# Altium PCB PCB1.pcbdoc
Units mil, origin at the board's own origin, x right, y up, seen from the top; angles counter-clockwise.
Board outline 4565 x 3530 mil, 4 copper layers (Top Layer, Inner1, Inner2, Bottom Layer); 96 components, 68 nets, 367 pads, 177 vias.
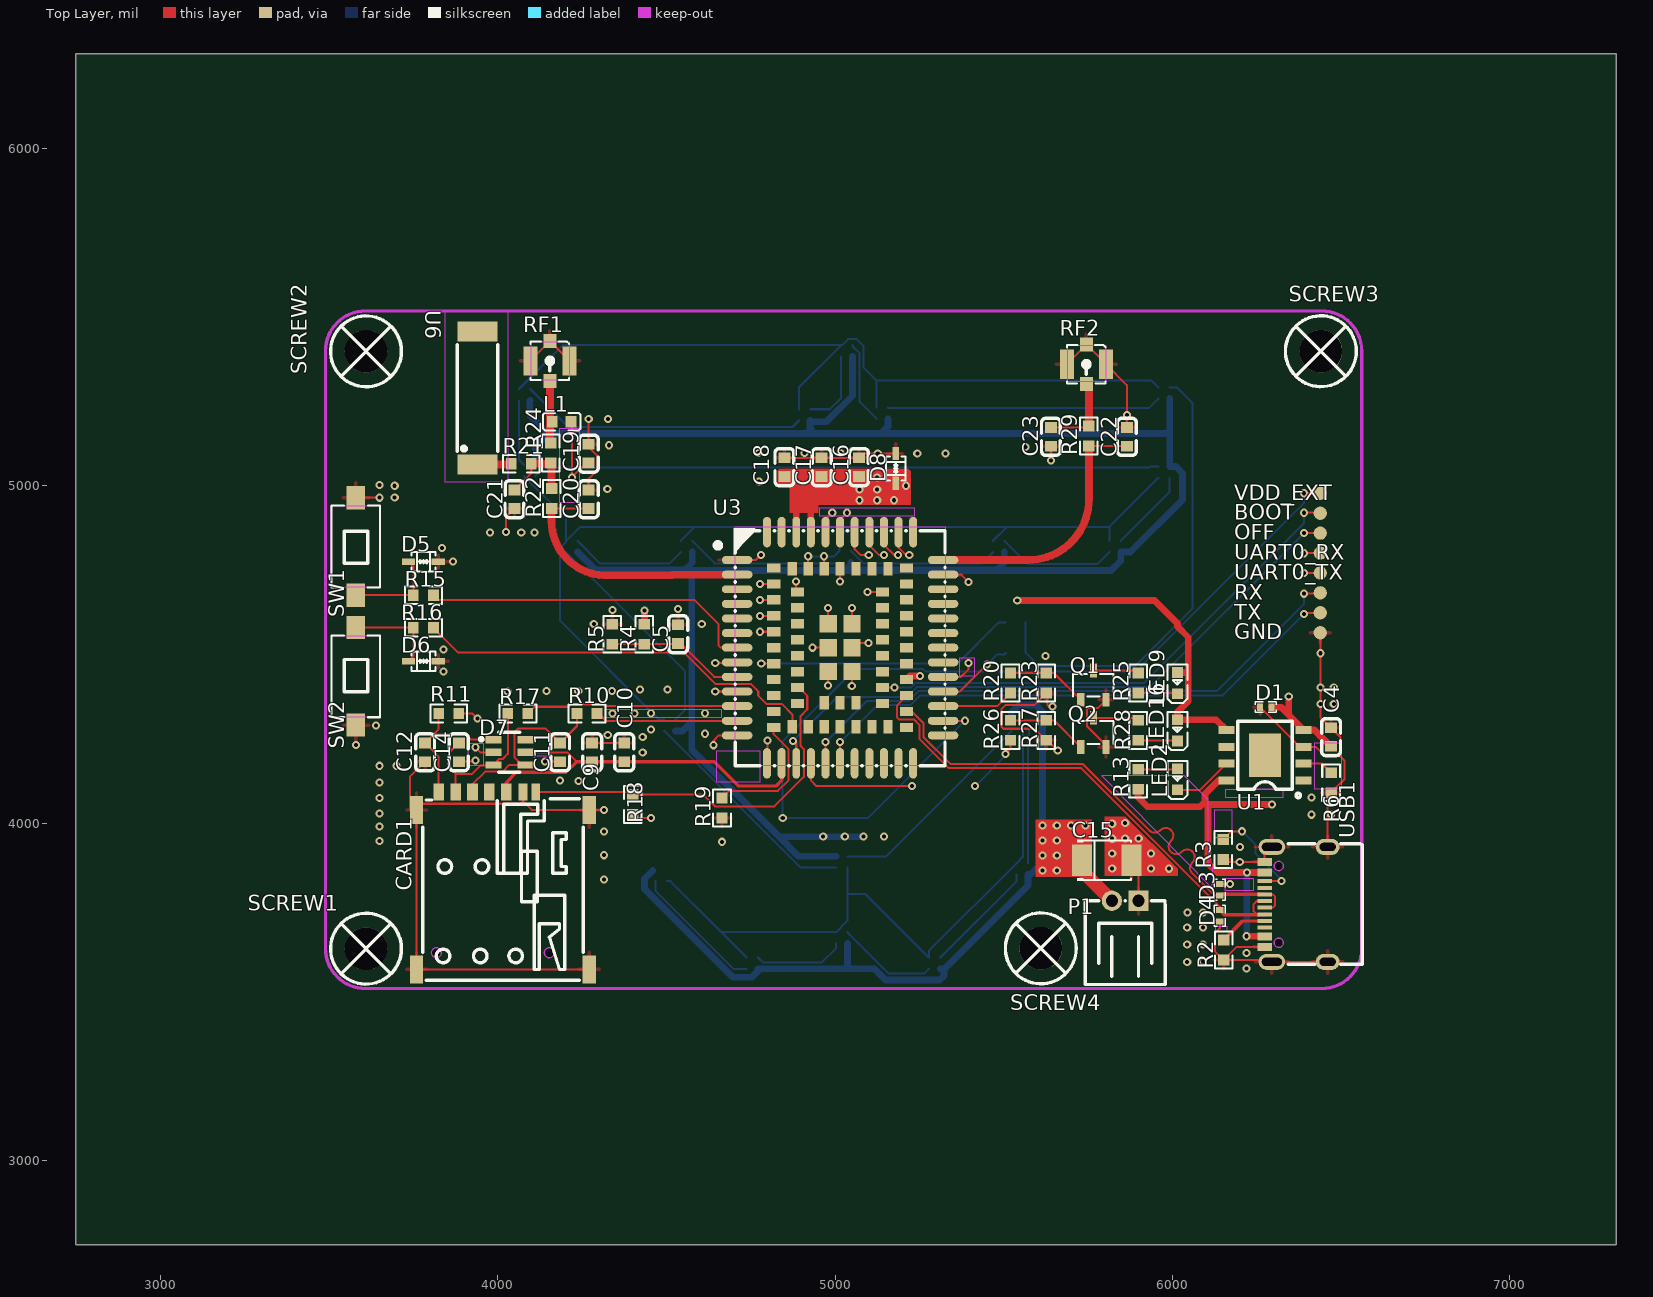
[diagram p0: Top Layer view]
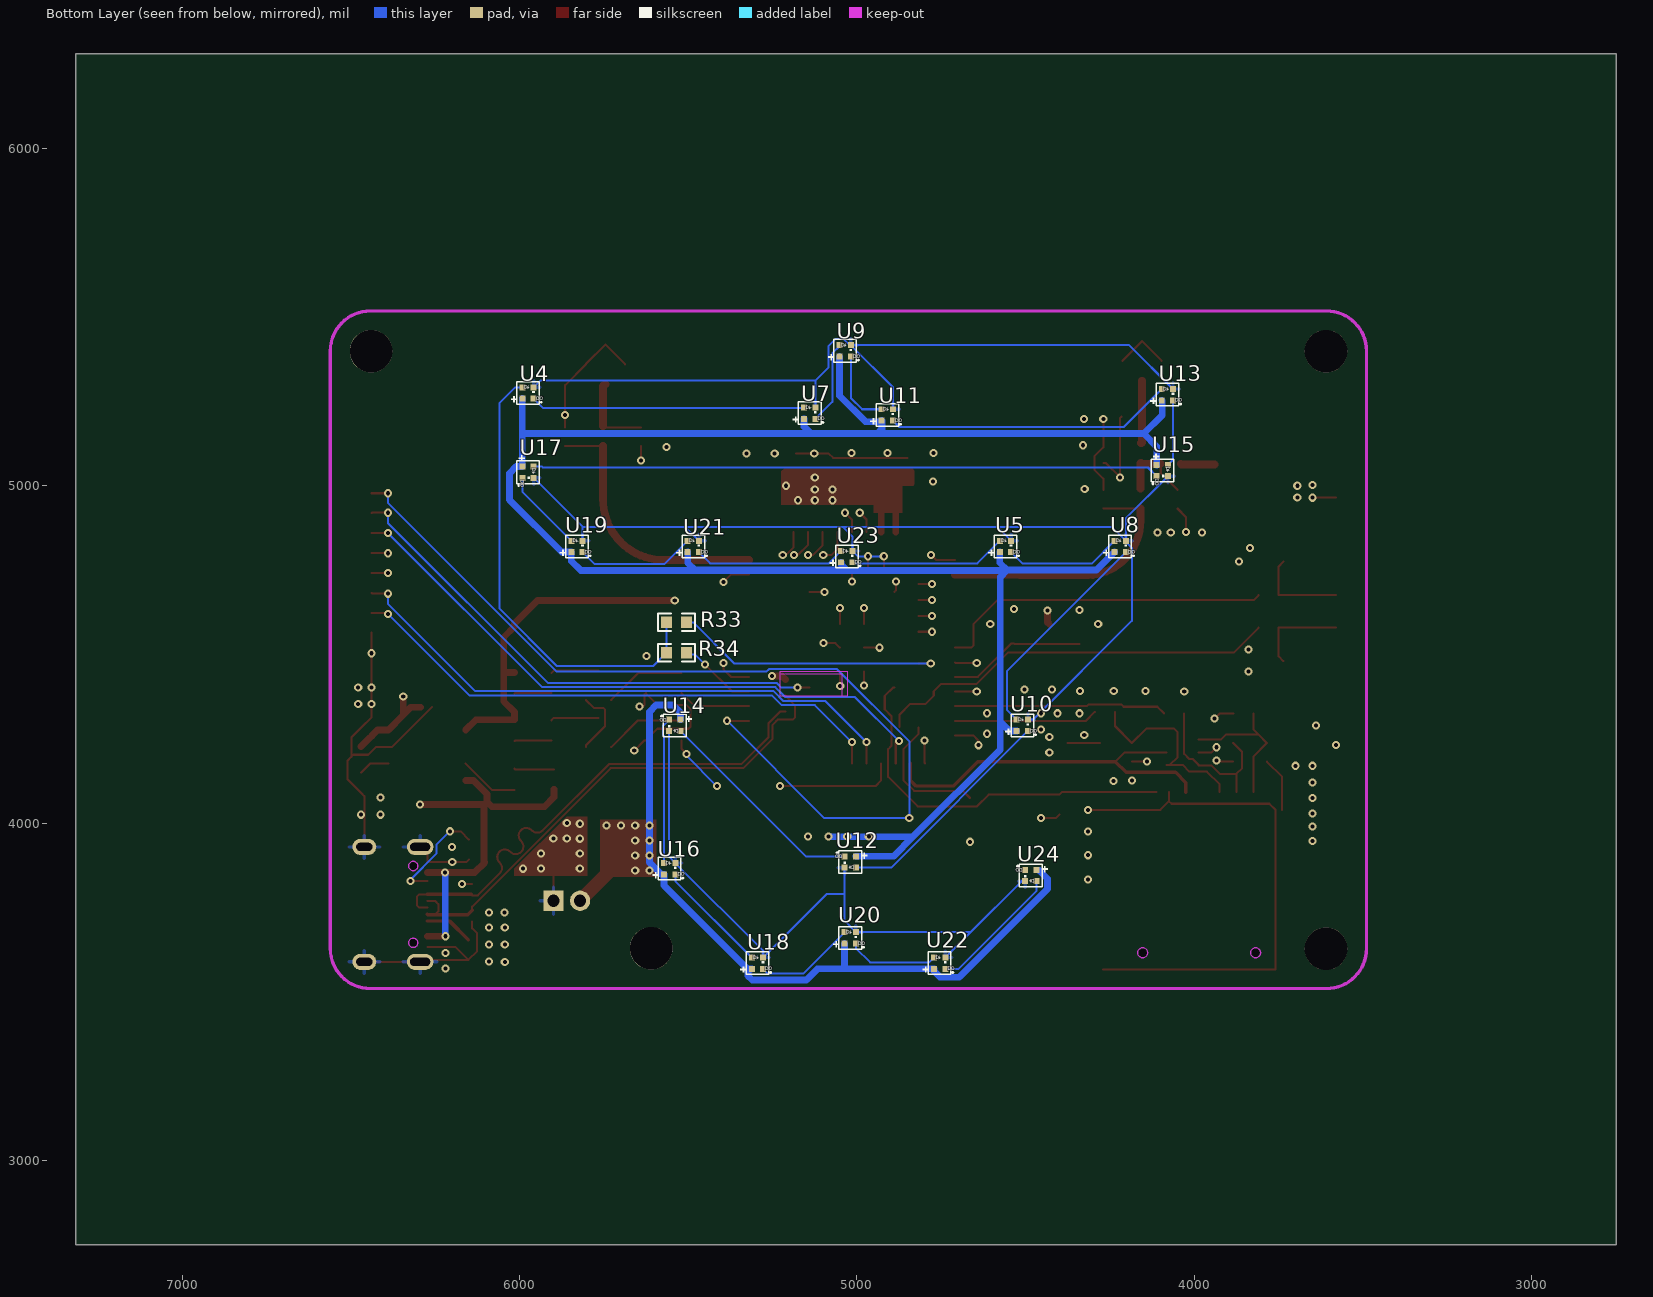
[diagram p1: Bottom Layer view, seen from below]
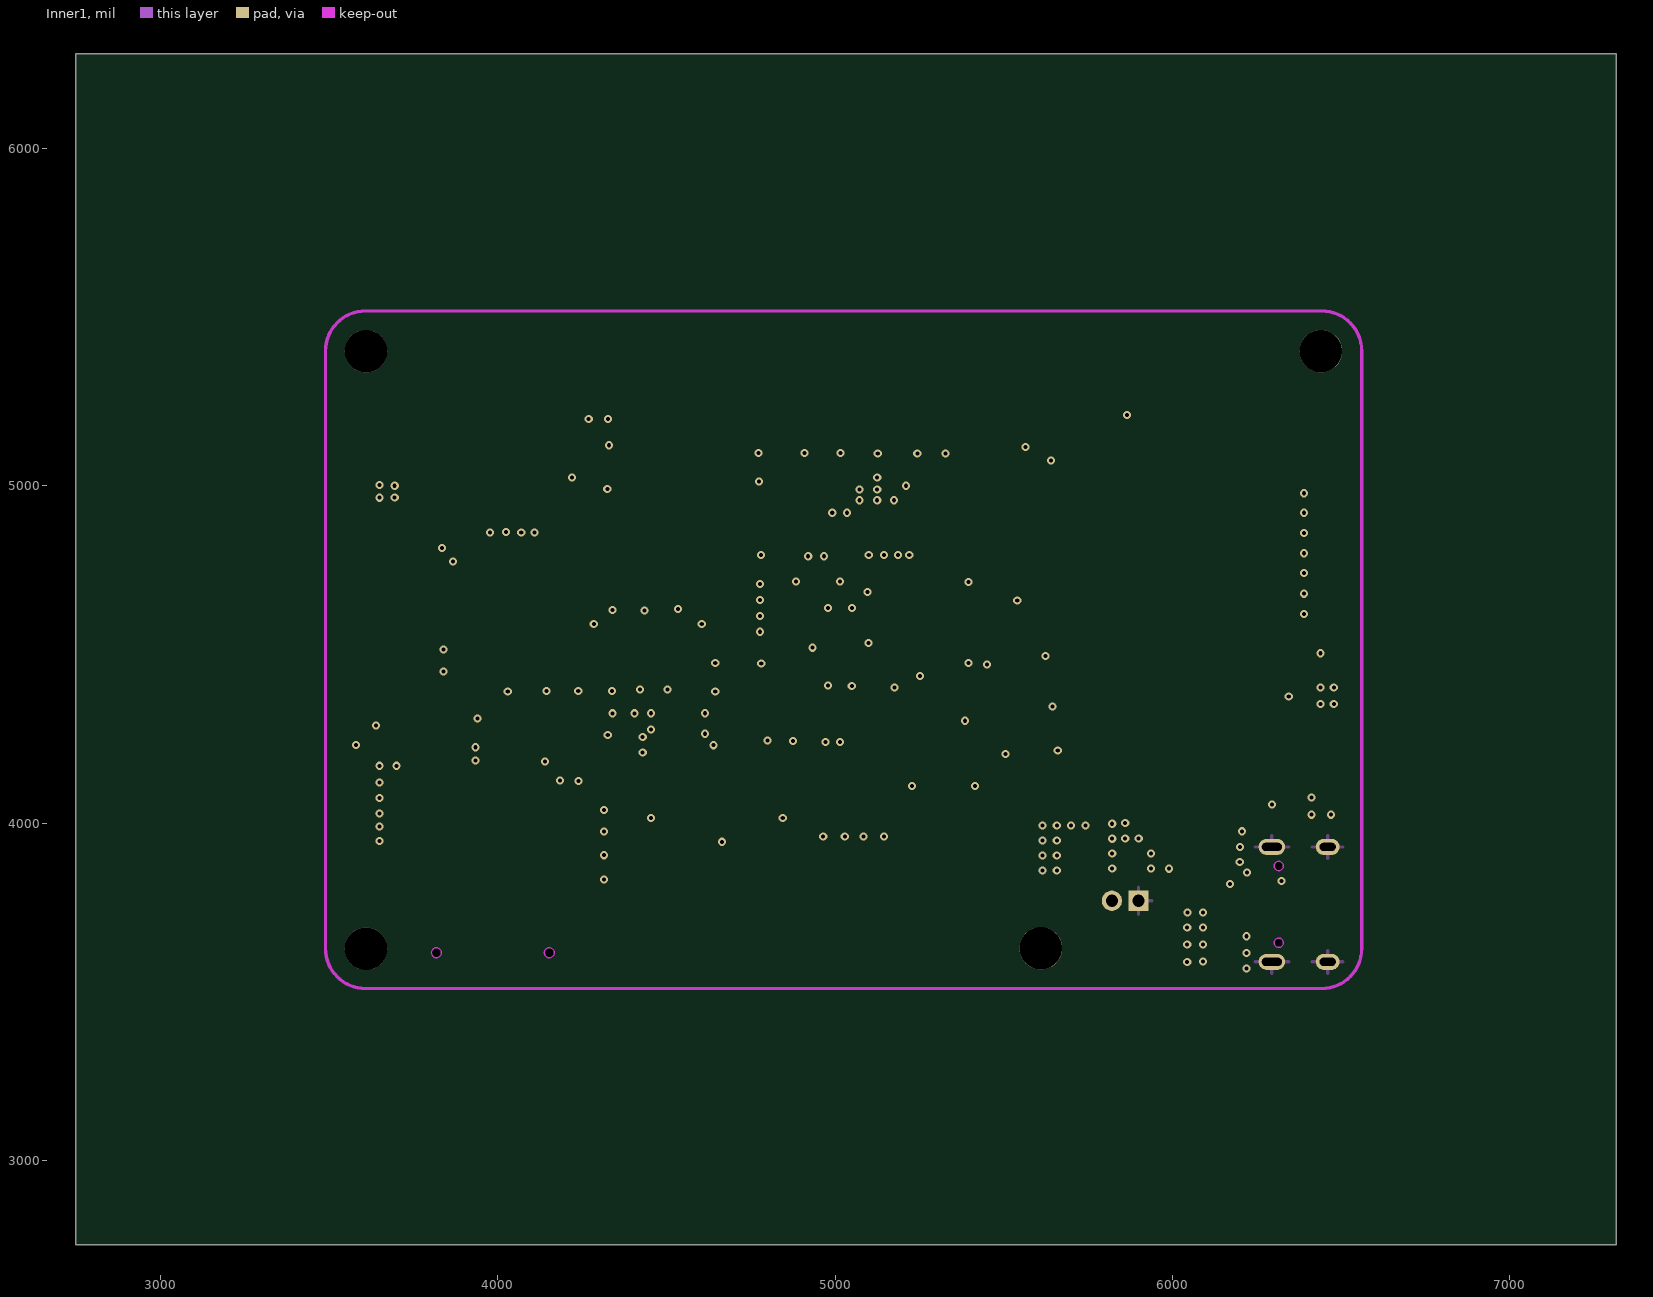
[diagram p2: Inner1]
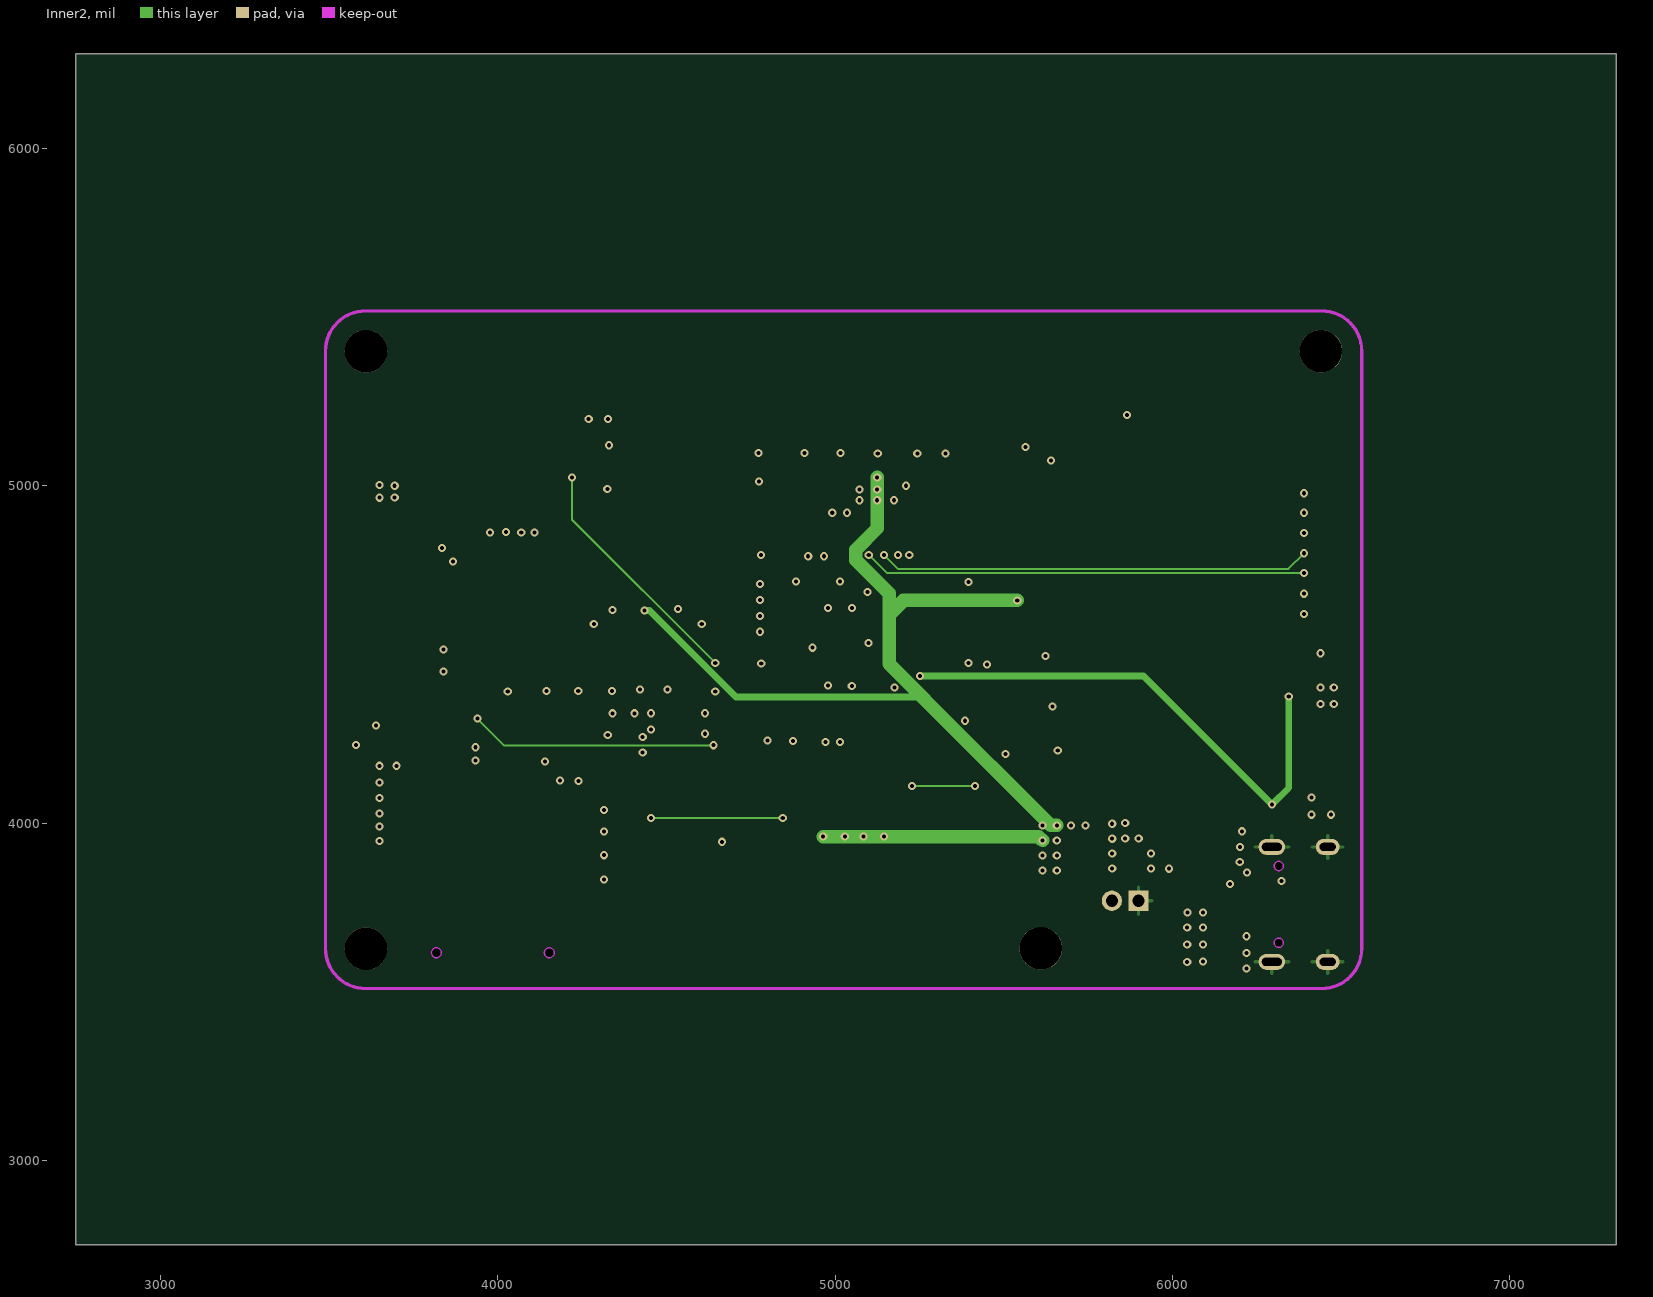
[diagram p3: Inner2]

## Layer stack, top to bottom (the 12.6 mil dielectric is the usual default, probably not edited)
Top Layer: signal copper (thickness not stored)
Dielectric: dielectric 12.6, FR-4, Dk 4.8
Inner1: signal copper (thickness not stored)
Dielectric: dielectric 12.6, FR-4, Dk 4.8
Inner2: signal copper (thickness not stored)
Dielectric: dielectric 12.6, FR-4, Dk 4.8
Bottom Layer: signal copper (thickness not stored)

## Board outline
7315,2750 2750,2750 2750,6280 7315,6280

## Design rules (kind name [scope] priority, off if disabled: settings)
BoardOutlineClearance copperThickness1oz [All] p0: genericclearance=10 ignorepadtopadclearanceinfootprint=FALSE except(0: Arc-SplitContinuation Track-SplitContinuation SMDPad-SplitContinuation THPad-SplitContinuation Via-SplitContinuation Fill-SplitContinuation Poly-SplitContinuation Region-SplitContinuation Text-SplitContinuation; 6: Track-CutoutEdge SMDPad-CutoutEdge THPad-CutoutEdge Via-CutoutEdge Region-CutoutEdge; 11.8: Track-OutlineEdge SMDPad-OutlineEdge THPad-OutlineEdge Via-OutlineEdge Fill-OutlineEdge Region-OutlineEdge Poly-OutlineEdge Text-OutlineEdge Fill-CutoutEdge)
BoardOutlineClearance copperThickness2oz [All] p0: genericclearance=10 ignorepadtopadclearanceinfootprint=FALSE except(0: Arc-SplitContinuation Track-SplitContinuation SMDPad-SplitContinuation THPad-SplitContinuation Via-SplitContinuation Fill-SplitContinuation Poly-SplitContinuation Region-SplitContinuation Text-SplitContinuation; 6: Track-CutoutEdge SMDPad-CutoutEdge THPad-CutoutEdge Via-CutoutEdge Region-CutoutEdge; 11.8: Track-OutlineEdge SMDPad-OutlineEdge THPad-OutlineEdge Via-OutlineEdge Fill-OutlineEdge Region-OutlineEdge Poly-OutlineEdge Text-OutlineEdge Fill-CutoutEdge)
Clearance copperThickness1oz [(InNet('GND') OR InNet('GNSS_ANT') OR InNet('GNSS_VCC') OR InNet('ADC0') OR InNet('SIM_DATA') OR InNet('SIM_RST') OR InNet('SIM_CLK') OR InNet('SIM_VCC') OR InNet('POWER_OFF') OR InNet('NET_STATUS') OR InNet('RX') OR InNet('TX') OR InNet('STATUS') OR InNet('PWM0') OR InNet('LTE_ANT') OR InNet('DBG_RX') OR InNet('DBG_TX') OR InNet('VBAT') OR InNet('USB_P') OR InNet('USB_N') OR InNet('VBUS') OR InNet('SIM_DET') OR InNet('BOOT') OR InNet('$1N12616') OR InNet('$1N23115') OR InNet('$1N19552') OR InNet('$1N23022') OR InNet('$1N11177') OR InNet('$1N11181') OR InNet('$1N19973') OR InNet('$1N20292') OR InNet('$1N19953') OR InNet('$1N19963') OR InNet('$1N20297') OR InNet('$1N20301') OR InNet('$1N2306') OR InNet('$1N2310') OR InNet('$1N11019') OR InNet('$1N23131') OR InNet('$1N25527') OR InNet('$1N25532') OR InNet('$1N25538') OR InNet('$1N25544') OR InNet('$1N25550') OR InNet('$1N25556') OR InNet('$1N25562') OR InNet('$1N25568') OR InNet('$1N25574') OR InNet('$1N26109') OR InNet('$1N26106') OR InNet('$1N26094') OR InNet('$1N26088') OR InNet('$1N26091') OR InNet('$1N26097') OR InNet('$1N26100') OR InNet('$1N26103') OR InNet('$1N26075') OR InNet('$1N26112') OR InNet('$1N29399') OR InNet('$1N32620') OR InNet('$1N32608') OR InNet('$1N42777') OR InNet('PWR_KEY') OR InNet('WAKEUP_KEY') OR InNet('$1N42623') OR InNet('VDD_EXT') OR InNet('SPI0_MOSI') OR InNet('WS2812_DIN'))] p1: gap=7 ignorepadtopadclearanceinfootprint=FALSE except(6: Track-Track Track-SMDPad SMDPad-SMDPad Track-THPad SMDPad-THPad THPad-THPad Track-Via SMDPad-Via THPad-Via Via-Via Track-Fill SMDPad-Fill THPad-Fill Via-Fill Fill-Fill Track-Region SMDPad-Region THPad-Region Via-Region Region-Region Track-Poly SMDPad-Poly THPad-Poly Via-Poly Fill-Poly Region-Poly Poly-Poly Track-Text SMDPad-Text THPad-Text Via-Text Fill-Text Region-Text Poly-Text Text-Text; 6.9: Track-Hole SMDPad-Hole THPad-Hole Via-Hole Fill-Hole Region-Hole Poly-Hole Text-Hole Sheet-Hole; 11.8: Fill-Region Track-Sheet SMDPad-Sheet THPad-Sheet Via-Sheet Fill-Sheet Region-Sheet Poly-Sheet Text-Sheet)
Clearance copperThickness2oz [All] p1: gap=7 ignorepadtopadclearanceinfootprint=FALSE except(6: Track-SMDPad SMDPad-SMDPad Track-THPad SMDPad-THPad THPad-THPad Track-Via SMDPad-Via THPad-Via Via-Via SMDPad-Fill THPad-Fill Via-Fill Fill-Fill Track-Region SMDPad-Region THPad-Region Via-Region Region-Region Track-Poly SMDPad-Poly THPad-Poly Via-Poly Fill-Poly Region-Poly Poly-Poly Track-Text SMDPad-Text THPad-Text Via-Text Fill-Text Region-Text Poly-Text Text-Text; 6.9: Track-Hole SMDPad-Hole THPad-Hole Via-Hole Fill-Hole Region-Hole Poly-Hole Text-Hole Sheet-Hole; 8: Track-Track; 11.8: Track-Fill Fill-Region Track-Sheet SMDPad-Sheet THPad-Sheet Via-Sheet Fill-Sheet Region-Sheet Poly-Sheet Text-Sheet)
DiffPairsRouting differentialPair [All] p1: maxuncoupledlength=10 minlimit=6 maxlimit=6 mostfreqgap=6 toplayer_minwidth=5 toplayer_prefwidth=6 toplayer_maxwidth=100 bottomlayer_minwidth=5 bottomlayer_prefwidth=6 bottomlayer_maxwidth=100 midlayer1_minwidth=5 midlayer1_prefwidth=6 midlayer1_maxwidth=100 midlayer2_minwidth=5 midlayer2_prefwidth=6 midlayer2_maxwidth=100
PasteMaskExpansion pasteMaskExpansion [All] p1: expansion=0
PlaneConnect innerPlane [All] p1: planeconnectstyle=Relief reliefexpansion=20 reliefentries=4 reliefconductorwidth=10 reliefairgap=10
PolygonConnect copperRegion [All] p1: connectstyle=Relief reliefentries=4 reliefconductorwidth=10 polygonreliefangle="90 Angle" airgapwidth=10
RoutingVias viaSize [All] p1: viastyle="Through Hole" holewidth=12.0078 minholewidth=11.811 maxholewidth=248.0314 width=24.0158 minwidth=19.685 maxwidth=393.7008
SolderMaskExpansion solderMaskExpansion [All] p1: useseparateexpansions=TRUE expansion=2 expansionbottom=2
Width copperThickness1oz [All] p1: maxlimit=100 minlimit=5 preferedwidth=6
Width copperThickness2oz [All] p1: maxlimit=100 minlimit=8 preferedwidth=10
Width Power [All] p1: maxlimit=100 minlimit=20 preferedwidth=20
Width ANT [All] p1: maxlimit=100 minlimit=5 preferedwidth=23

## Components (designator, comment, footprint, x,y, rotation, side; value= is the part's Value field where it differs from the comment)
BOOT "测试点1.0mm" TP_10 6438.21,4918.68 r0 top
C4 "CL10A106KP8NNNC" C0603 6470,4255 r270 top
C5 "CC0603KRX7R9BB104" C0603 4535,4560 r270 top
C9 "CC0603KRX7R9BB104" C0603 4280.14,4210 r270 top
C10 "CL10C330JB8NNNC" C0603 4375.28,4210 r270 top
C11 "CL10C330JB8NNNC" C0603 4185,4210 r90 top
C12 "CL10C330JB8NNNC" C0603 3785,4210 r90 top
C14 "CL10C330JB8NNNC" C0603 3885,4210 r90 top
C15 "TLJB227M006R0500" CASE-B_3528 5805,3890 r0 top
C16 "CC0603KRX7R9BB104" C0603 5070.91,5055 r270 top
C17 "CL10C330JB8NNNC" C0603 4960.45,5055 r270 top
C18 "CL10C100JB8NNNC" C0603 4850,5055 r270 top
C19 "CC0603KRX7R9BB104" C0603 4270,5095 r270 top
C20 "NC" C0603 4270,4960 r270 top
C21 "NC" C0603 4050,4960 r90 top
C22 "NC" C0603 5865,5145 r270 top
C23 "NC" C0603 5640,5145 r90 top
CARD1 "SMN-303" SIM-SMD_SMN-303 4015.56,3829.41 r0 top
D1 "PESDMC2FD5VB" DFN1006-2L-BI 6276.72,4343.74 r0 top
D3 "PESDMC2FD5VB" DFN1006-2L-BI 6140.26,3802.89 r270 top
D4 "PESDMC2FD5VB" DFN1006-2L-BI 6140.26,3725.58 r90 top
D5 "PTVSHC3D4V5BH" SOD-323_L1.8-W1.3-LS2.5-BI 3780,4775 r0 top
D6 "PTVSHC3D4V5BH" SOD-323_L1.8-W1.3-LS2.5-BI 3780,4480 r0 top
D7 "SRV05-4_C7420376" SOT-23-6_L2.9-W1.6-P0.95-LS2.8-BL-1 4035,4210 r270 top
D8 "PTVSHC3D4V5BH" SOD-323_L1.8-W1.3-LS2.5-BI 5180,5051.33 r270 top
GND "测试点1.0mm" TP_10 6438.21,4564.35 r0 top
L1 "SDCL1608C4N7STDF" L0603 4190,5190 r180 top
LED2 "KT-0603R" LED0603-RD 6015,4130 r90 top
LED9 "KT-0603R" LED0603-RD 6015,4415 r90 top
LED16 "KT-0603R" LED0603-RD 6015,4274.84 r90 top
OFF "测试点1.0mm" TP_10 6438.21,4859.62 r0 top
P1 "WAFER-PH2.0-2PWZ" CONN-TH_2P-P2.00_GP01-2001WR-2P 5860,3770 r180 top
Q1 "S8050 J3Y(RANGE:200-350)" SOT-23-3_L3.0-W1.7-P0.95-LS2.9-BR 5765.63,4408.91 r270 top
Q2 "S8050 J3Y(RANGE:200-350)" SOT-23-3_L3.0-W1.7-P0.95-LS2.9-BR 5765.63,4268.75 r270 top
R2 "0603WAF5101T5E" R0603 6151.52,3624.23 r90 top
R3 "0603WAF5101T5E" R0603 6150.23,3921.69 r90 top
R4 "0603WAF4702T5E" R0603 4435,4560 r270 top
R5 "0603WAF1502T5E" R0603 4340,4560 r270 top
R6 "0603WAF2201T5E" R0603 6470,4120 r270 top
R10 "0603WAF220JT5E" R0603 4265,4325 r180 top
R11 "0603WAF220JT5E" R0603 3855,4325 r180 top
R13 "0603WAF1002T5E" R0603 5897.99,4130 r270 top
R15 "0603WAF1001T5E" R0603 3780,4675.81 r0 top
R16 "0603WAF1001T5E" R0603 3780,4579.19 r0 top
R17 "0603WAF220JT5E" R0603 4060,4325 r180 top
R18 "0603WAF1003T5E" R0603 4400,4055 r270 top
R19 "0603WAF1001T5E" R0603 4665,4045 r90 top
R20 "0603WAF4701T5E" R0603 5520,4415.16 r90 top
R21 "0603WAF0000T5E" R0603 4070,5065 r180 top
R22 "0603WAF0000T5E" R0603 4160,4962.19 r90 top
R23 "0603WAF4702T5E" R0603 5625.78,4415.16 r270 top
R24 "0603WAF0000T5E" R0603 4158.03,5097.19 r90 top
R25 "0603WAF2201T5E" R0603 5897.99,4415.16 r90 top
R26 "0603WAF4701T5E" R0603 5520,4275 r90 top
R27 "0603WAF4702T5E" R0603 5625.78,4275 r270 top
R28 "0603WAF2201T5E" R0603 5897.99,4275 r90 top
R29 "0603WAF0000T5E" R0603 5752.5,5147.19 r90 top
R33 "0603WAF0000T5E" R0603 5535,4595 r180 bottom
R34 "0603WAF0000T5E" R0603 5535,4505 r180 bottom
RF1 "HC-RF-IPEX0303-01" IPEX-SMD_HC-RF-IPEX0303-01 4155,5370 r0 top
RF2 "HC-RF-IPEX0303-01" IPEX-SMD_HC-RF-IPEX0303-01 5745,5360 r0 top
RX "测试点1.0mm" TP_10 6438.21,4682.46 r0 top
SCREW1 "M3螺丝" M3螺丝 3609.9,3628.05 r0 top
SCREW2 "M3螺丝" M3螺丝 3609.9,5398.36 r0 top
SCREW3 "M3螺丝" M3螺丝 6439.9,5398.68 r0 top
SCREW4 "M3螺丝" M3螺丝 5609.9,3628.99 r0 top
SW1 "TSB013A4326A02" SW-SMD_L6.0-W3.5-LS8.0 3580,4820 r270 top
SW2 "TSB013A4326A02" SW-SMD_L6.0-W3.5-LS8.0 3580,4435 r90 top
TX "测试点1.0mm" TP_10 6438.21,4623.4 r0 top
U1 "TP4056_C725790" ESOP-8_L4.9-W3.9-P1.27-LS6.0-BL-EP 6274.28,4201.4 r90 top
U3 "AIR780EG_C9900042550_C9900081146" LCC-109_L17.7-W15.8-P1.10_EC800M-CN 5015,4520 r0 top locked
U4 "XL-1010RGBC-WS2812B" LED-SMD_4P-L1.0-W1.0-TL_XL-1010RGBC-WS2812B 5975,5275 r0 bottom
U5 "XL-1010RGBC-WS2812B" LED-SMD_4P-L1.0-W1.0-TL_XL-1010RGBC-WS2812B 4560,4820 r0 bottom
U6 "GPS1003" ANT-SMD_L10.0-W3.0 3940,5260 r90 top
U7 "XL-1010RGBC-WS2812B" LED-SMD_4P-L1.0-W1.0-TL_XL-1010RGBC-WS2812B 5140,5215 r0 bottom
U8 "XL-1010RGBC-WS2812B" LED-SMD_4P-L1.0-W1.0-TL_XL-1010RGBC-WS2812B 4220,4820 r0 bottom
U9 "XL-1010RGBC-WS2812B" LED-SMD_4P-L1.0-W1.0-TL_XL-1010RGBC-WS2812B 5035,5400 r0 bottom
U10 "XL-1010RGBC-WS2812B" LED-SMD_4P-L1.0-W1.0-TL_XL-1010RGBC-WS2812B 4510,4290 r0 bottom
U11 "XL-1010RGBC-WS2812B" LED-SMD_4P-L1.0-W1.0-TL_XL-1010RGBC-WS2812B 4910,5210 r0 bottom
U12 "XL-1010RGBC-WS2812B" LED-SMD_4P-L1.0-W1.0-TL_XL-1010RGBC-WS2812B 5020,3885 r180 bottom
U13 "XL-1010RGBC-WS2812B" LED-SMD_4P-L1.0-W1.0-TL_XL-1010RGBC-WS2812B 4080,5270 r0 bottom
U14 "XL-1010RGBC-WS2812B" LED-SMD_4P-L1.0-W1.0-TL_XL-1010RGBC-WS2812B 5540,4290 r180 bottom
U15 "XL-1010RGBC-WS2812B" LED-SMD_4P-L1.0-W1.0-TL_XL-1010RGBC-WS2812B 4095,5045 r90 bottom
U16 "XL-1010RGBC-WS2812B" LED-SMD_4P-L1.0-W1.0-TL_XL-1010RGBC-WS2812B 5555,3865 r0 bottom
U17 "XL-1010RGBC-WS2812B" LED-SMD_4P-L1.0-W1.0-TL_XL-1010RGBC-WS2812B 5975,5040 r90 bottom
U18 "XL-1010RGBC-WS2812B" LED-SMD_4P-L1.0-W1.0-TL_XL-1010RGBC-WS2812B 5295,3585 r0 bottom
U19 "XL-1010RGBC-WS2812B" LED-SMD_4P-L1.0-W1.0-TL_XL-1010RGBC-WS2812B 5830,4820 r0 bottom
U20 "XL-1010RGBC-WS2812B" LED-SMD_4P-L1.0-W1.0-TL_XL-1010RGBC-WS2812B 5020,3660 r0 bottom
U21 "XL-1010RGBC-WS2812B" LED-SMD_4P-L1.0-W1.0-TL_XL-1010RGBC-WS2812B 5485,4820 r0 bottom
U22 "XL-1010RGBC-WS2812B" LED-SMD_4P-L1.0-W1.0-TL_XL-1010RGBC-WS2812B 4755,3585 r0 bottom
U23 "XL-1010RGBC-WS2812B" LED-SMD_4P-L1.0-W1.0-TL_XL-1010RGBC-WS2812B 5030,4790 r0 bottom
U24 "XL-1010RGBC-WS2812B" LED-SMD_4P-L1.0-W1.0-TL_XL-1010RGBC-WS2812B 4485,3845 r180 bottom
UART0_RX "测试点1.0mm" TP_10 6438.21,4800.57 r0 top
UART0_TX "测试点1.0mm" TP_10 6438.21,4741.51 r0 top
USB1 "TYPE-C 16PIN 2MD(073)" USB-C-SMD_TYPE-C-6PIN-2MD-073 6366.52,3759.23 r90 top
VDD_EXT "测试点1.0mm" TP_10 6438.21,4977.73 r0 top

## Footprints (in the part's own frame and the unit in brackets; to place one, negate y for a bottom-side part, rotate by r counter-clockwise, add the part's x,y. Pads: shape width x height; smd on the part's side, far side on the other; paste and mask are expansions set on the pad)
ANT-SMD_L10.0-W3.0 [mm]
  rect 1.5x3 smd: 1(-5,0) 2(5,0)
  silkscreen extent -4.02,-1.52 4.02,1.52
C0603 [mm]
  rect 0.8x0.9 smd: 1(-0.7,0) 2(0.7,0)
  silkscreen extent -1.39,-0.71 1.39,0.71
CASE-B_3528 [mil]
  rect 59.3x93.54 smd: 1(-73.25,0) 2(73.25,0)
  silkscreen extent -87,-61 72,61
CONN-TH_2P-P2.00_GP01-2001WR-2P [mil]
  rect 60x60 hole 36: 1(-39.37,0)
  round 60 hole 36: 2(39.37,0)
  silkscreen extent -118,0 118,248
DFN1006-2L-BI [mm]
  rect 0.45x0.55 smd: 1(-0.425,0) 2(0.425,0)
  silkscreen extent -0.8,-0.4 0.8,0.4
ESOP-8_L4.9-W3.9-P1.27-LS6.0-BL-EP [mm]
  rect 0.6x1.2 smd: 1(-1.905,-2.908) 2(-0.635,-2.908) 3(0.635,-2.908) 4(1.905,-2.908) 5(1.905,2.908) 6(0.635,2.908) 7(-0.635,2.908) 8(-1.905,2.908)
  rect 3.3x2.4 smd: 9(0,0)
  silkscreen extent -3.2,-2.67 2.55,2.05
IPEX-SMD_HC-RF-IPEX0303-01 [mm]
  rect 1x1.05 smd: 1(0,-1.5) 4(0,1.5)
  rect 1.05x2.2 smd: 2(1.475,0) 3(-1.475,0)
  silkscreen extent -1.45,-1.45 1.45,1.45
L0603 [mm]
  rect 0.8x0.864 smd: 1(-0.7,0) 2(0.7,0)
  silkscreen extent -1.42,-0.65 1.42,0.65
LCC-109_L17.7-W15.8-P1.10_EC800M-CN [mm]
  oval 2.3x0.6 smd: 1(-7.75,6.6) 2(-7.75,5.5) 3(-7.75,4.4) 4(-7.75,3.3) 5(-7.75,2.2) 6(-7.75,1.1) 7(-7.75,0) 8(-7.75,-1.1) 9(-7.75,-2.2) 10(-7.75,-3.3) 11(-7.75,-4.4) 12(-7.75,-5.5) 13(-7.75,-6.6) 23(7.75,-6.6) 24(7.75,-5.5) 25(7.75,-4.4) 26(7.75,-3.3) 27(7.75,-2.2) 28(7.75,-1.1) 29(7.75,0) 30(7.75,1.1) 31(7.75,2.2) 32(7.75,3.3) 33(7.75,4.4) 34(7.75,5.5) 35(7.75,6.6)
  oval 0.6x2.3 smd: 14(-4.4,-8.7) 15(-3.3,-8.7) 16(-2.2,-8.7) 17(-1.1,-8.7) 18(0,-8.7) 19(1.1,-8.7) 20(2.2,-8.7) 21(3.3,-8.7) 22(4.4,-8.7) 36(4.4,8.7) 37(3.3,8.7) 38(2.2,8.7) 39(1.1,8.7) 40(0,8.7) 41(-1.1,8.7) 42(-2.2,8.7) 43(-3.3,8.7) 44(-4.4,8.7) 95(-5.5,-8.7) 96(5.5,-8.7) 97(5.5,8.7) 98(-5.5,8.7)
  rect 1x0.7 smd: 45(-5,4.8) 46(-5,3.6) 47(-5,2.4) 48(-5,1.2) 49(-5,0) 50(-5,-1.2) 51(-5,-2.4) 52(-5,-3.6) 53(-5,-4.8) 59(5,-4.8) 60(5,-3.6) 61(5,-2.4) 62(5,-1.2) 63(5,0) 64(5,1.2) 65(5,2.4) 66(5,3.6) 67(5,4.8) 73(-3.2,4.2) 74(-3.2,3) 75(-3.2,1.8) 76(-3.2,0.6) 77(-3.2,-0.6) 78(-3.2,-1.8) 79(-3.2,-3) 80(-3.2,-4.2) 81(3.2,-4.2) 82(3.2,-3) 83(3.2,-1.8) 84(3.2,-0.6) 85(3.2,0.6) 86(3.2,1.8) 87(3.2,3) 88(3.2,4.2) 99(-5,6) 100(-5,-6) 103(5,-6) 104(5,6)
  rect 0.7x1 smd: 54(-2.4,-5.95) 55(-1.2,-5.95) 56(0,-5.95) 57(1.2,-5.95) 58(2.4,-5.95) 68(2.4,5.95) 69(1.2,5.95) 70(0,5.95) 71(-1.2,5.95) 72(-2.4,5.95) 101(-3.6,-5.95) 102(3.6,-5.95) 105(3.6,5.95) 106(-3.6,5.95) 107(-1.2,-4.15) 108(0,-4.15) 109(1.2,-4.15)
  rect 1.3x1.3 smd: 89(-0.9,1.8) 90(-0.9,0) 91(-0.9,-1.8) 92(0.9,-1.8) 93(0.9,0) 94(0.9,1.8)
  silkscreen extent -9.4,-8.9 7.9,9
LED0603-RD [mm]
  rect 0.8x0.8 smd: 1(-0.799,0) 2(0.799,0)
  silkscreen extent -1.49,-0.75 1.39,0.76
LED-SMD_4P-L1.0-W1.0-TL_XL-1010RGBC-WS2812B [mm]
  rect 0.45x0.45 smd: 1(-0.425,0.425) 2(0.425,0.425) 3(-0.425,-0.425) 4(0.425,-0.425)
  silkscreen extent -1.05,-0.85 1.27,0.85
M3螺丝 [mil]
  round 126 hole 126: 1(0,0)
  silkscreen extent -105,-105 105,105
R0603 [mil]
  rect 31.75x34.02 smd: 1(-29.66,0) 2(29.66,0)
  silkscreen extent -55,-26 55,26
SIM-SMD_SMN-303 [mm]
  rect 1x2.1 smd: 8(-6.5,5.328) 9(6.5,5.328) 10(6.5,-6.672) 11(-6.5,-6.672)
  rect 0.8x1.3 smd: C1(0.25,6.672) C2(-2.29,6.672) C3(-4.83,6.672) C6(-1.02,6.672) C7(-3.56,6.672)
  rect 0.65x1.3 smd: C5(1.52,6.672) CD(2.47,6.672)
  Board Outline Layer circle w0.005: c-5,-5.422 r0.375
  Board Outline Layer circle w0.005: c3.5,-5.422 r0.375
  Board Outline Layer region: -4.625,-5.422 -4.662,-5.585 -4.766,-5.715 -4.916,-5.788 -5.083,-5.788 -5.234,-5.715 -5.338,-5.585 -5.375,-5.422 -5.375,-5.422 -5.338,-5.259 -5.234,-5.129 -5.083,-5.057 -4.916,-5.057 -4.766,-5.129 -4.662,-5.259 -4.625,-5.422
  Board Outline Layer region: 3.875,-5.422 3.838,-5.585 3.734,-5.715 3.583,-5.788 3.417,-5.788 3.266,-5.715 3.162,-5.585 3.125,-5.422 3.125,-5.422 3.162,-5.259 3.266,-5.129 3.417,-5.057 3.583,-5.057 3.734,-5.129 3.838,-5.259 3.875,-5.422
  Multi-Layer board cut-out: -4.625,-5.422 -4.662,-5.585 -4.766,-5.715 -4.916,-5.788 -5.083,-5.788 -5.234,-5.715 -5.338,-5.585 -5.375,-5.422 -5.375,-5.422 -5.338,-5.259 -5.234,-5.129 -5.083,-5.057 -4.916,-5.057 -4.766,-5.129 -4.662,-5.259 -4.625,-5.422
  Multi-Layer board cut-out: 3.875,-5.422 3.838,-5.585 3.734,-5.715 3.583,-5.788 3.417,-5.788 3.266,-5.715 3.162,-5.585 3.125,-5.422 3.125,-5.422 3.162,-5.259 3.266,-5.129 3.417,-5.057 3.583,-5.057 3.734,-5.129 3.838,-5.259 3.875,-5.422
  silkscreen extent -6.04,-7.49 6.04,6.16
SOD-323_L1.8-W1.3-LS2.5-BI [mm]
  rect 0.985x0.49 smd: 1(-1.118,0) 2(1.118,0)
  silkscreen extent -0.9,-0.73 0.9,0.73
SOT-23-3_L3.0-W1.7-P0.95-LS2.9-BR [mil]
  rect 40.85x20.95 smd: 1(43.36,-37.4) 2(43.36,37.4) 3(-43.36,0)
  silkscreen extent -34,-60 34,60
SOT-23-6_L2.9-W1.6-P0.95-LS2.8-BL-1 [mm]
  rect 0.55x1.2 smd: 1(-0.95,-1.2) 2(0,-1.2) 3(0.95,-1.2) 4(0.95,1.2) 5(0,1.2) 6(-0.95,1.2)
  silkscreen extent -1.5,-2.25 1.5,0.8
SW-SMD_L6.0-W3.5-LS8.0 [mm]
  rect 1.74x1.4 smd: 1(-3.67,0) 2(3.67,0)
  silkscreen extent -3.08,-1.83 3.08,1.83
TP_10 [mm]
  round 1 smd: 1(0,0)
USB-C-SMD_TYPE-C-6PIN-2MD-073 [mm]
  rect 0.6x1.1 smd: 1(-3.2,2.375) 2(-2.4,2.375) 11(2.4,2.375) 12(3.2,2.375)
  rect 0.3x1.1 smd: 3(-1.75,2.375) 4(-1.25,2.375) 5(-0.75,2.375) 6(-0.25,2.375) 7(0.25,2.375) 8(0.75,2.375) 9(1.25,2.375) 10(1.75,2.375)
  oval 1.2x1.8 hole 0.6 slot 1.2 at 90 deg: 13(-4.325,-2.375) 14(4.325,-2.375)
  oval 1.2x2 hole 0.6 slot 1.5 at 90 deg: 13(-4.325,1.825) 14(4.325,1.825)
  Board Outline Layer circle w0.005: c-2.89,1.305 r0.35
  Board Outline Layer circle w0.005: c2.89,1.305 r0.35
  Board Outline Layer region: -2.89,0.955 -3.042,0.99 -3.164,1.087 -3.231,1.227 -3.231,1.383 -3.164,1.523 -3.042,1.62 -2.89,1.655 -2.89,1.655 -2.738,1.62 -2.616,1.523 -2.549,1.383 -2.549,1.227 -2.616,1.087 -2.738,0.99 -2.89,0.955
  Board Outline Layer region: 2.89,0.955 2.738,0.99 2.616,1.087 2.549,1.227 2.549,1.383 2.616,1.523 2.738,1.62 2.89,1.655 2.89,1.655 3.042,1.62 3.164,1.523 3.231,1.383 3.231,1.227 3.164,1.087 3.042,0.99 2.89,0.955
  Multi-Layer board cut-out: -2.89,0.955 -3.042,0.99 -3.164,1.087 -3.231,1.227 -3.231,1.383 -3.164,1.523 -3.042,1.62 -2.89,1.655 -2.89,1.655 -2.738,1.62 -2.616,1.523 -2.549,1.383 -2.549,1.227 -2.616,1.087 -2.738,0.99 -2.89,0.955
  Multi-Layer board cut-out: 2.89,0.955 2.738,0.99 2.616,1.087 2.549,1.227 2.549,1.383 2.616,1.523 2.738,1.62 2.89,1.655 2.89,1.655 3.042,1.62 3.164,1.523 3.231,1.383 3.231,1.227 3.164,1.087 3.042,0.99 2.89,0.955
  silkscreen extent -4.5,-4.97 4.57,0.6

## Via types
v1: diameter 24.02, hole 12.01, Top Layer to Bottom Layer, 177 vias

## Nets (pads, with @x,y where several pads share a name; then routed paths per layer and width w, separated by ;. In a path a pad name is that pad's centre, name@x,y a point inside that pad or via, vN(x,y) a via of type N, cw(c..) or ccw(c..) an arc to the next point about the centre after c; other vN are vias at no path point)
$1N2306: R2.2 USB1.4 | length 144.7
  Top Layer w10: R2.2 6207.65,3710.03 USB1.4
$1N2310: R3.2 USB1.10 | length 312.6
  Top Layer w6: R3.2 6174.82,3975.93 v1(6206.34,3975.93) ; USB1.10 v1(6323.14,3828.14)
  Bottom Layer w6: v1(6206.34,3975.93) 6246.31,3935.96 6246.31,3909.66 6323.14,3832.83 v1(6323.14,3828.14)
$1N11019: R6.1 U1.2 | length 92.3
  Top Layer w6: U1.2 6443.26,4176.4 R6.1
$1N11177: LED2.2 R13.1 | length 117.8
  Top Layer w6: R13.1 6013.18,4159.66 LED2.2
$1N11181: LED2.1 U1.7 | length 177
  Top Layer w6: LED2.1 6081.91,4098.52 U1.7
$1N12616: R19.2 U3.100 | length 394
  Top Layer w6: R19.2 4686.34,4096 4830.8,4096 4862.57,4127.77 4862.57,4219.56 4818.15,4263.97 U3.100
$1N19552: C23.2 R29.2 RF2.1 | length 242.7
  Top Layer w6: C23.2 5748.21,5172.56 R29.2
  Top Layer w23: RF2.1 cw(c5745,5293.45) 5752.5,5293.45 R29.2
$1N19953: Q1.1 R20.2 R23.1 | length 241.1
  Top Layer w6: R20.2 R23.1 5648.96,4444.82 Q1.1
$1N19963: Q1.3 R25.2 | length 142.9
  Top Layer w6: Q1.3 5898.04,4452.27 R25.2@5905.49,4444.82
$1N19973: LED9.1 R25.1 | length 110.3
  Top Layer w6: R25.1@5905.49,4385.51 6013.02,4385.51 LED9.1
$1N20292: LED16.1 R28.1 | length 110.3
  Top Layer w6: R28.1@5905.49,4245.34 6013.02,4245.34 LED16.1
$1N20297: Q2.1 R26.2 R27.1 | length 241.1
  Top Layer w6: R26.2 R27.1 5648.96,4304.66 Q2.1
$1N20301: Q2.3 R28.2 | length 142.9
  Top Layer w6: Q2.3 5898.04,4312.11 R28.2@5905.49,4304.66
$1N23022: L1.2 R24.2 RF1.1 | length 259.9
  Top Layer w6: RF1.1 4164.2,5301.75 4164.2,5245
  Top Layer w23: RF1.1 R24.2@4155,5129.88 ; R24.2@4155,5129.88 R24.2 cw(c4158.03,5129.88) R24.2@4155,5129.88
$1N23115: C21.2 R21.1 R22.2 R24.1 | length 234.2
  Top Layer w6: C21.2 4099.66,5037.22 R21.1
  Top Layer w23: R21.1 4155.5,5065 R24.1 cw(c4158.03,5065.56) 4160,5065.56 R22.2
$1N23131: R21.2 U6.1 | length 101.1
  Top Layer w23: U6.1 4038.49,5063.15 R21.2
$1N25527: U4.1 U7.4 | length 813.1
  Bottom Layer w6: U7.4 5157.47,5230.99 5930.98,5230.99 U4.1
$1N25532: U7.1 U9.4 | length 248.1
  Bottom Layer w6: U9.4 5051.73,5413.69 5073,5392.42 5073,5248.55 U7.1
$1N25538: U9.1 U11.4 | length 228.5
  Bottom Layer w6: U11.4 4984.86,5226.73 5018.27,5260.14 U9.1
$1N25544: U11.1 U13.4 | length 851.2
  Bottom Layer w6: U13.4 4209.46,5174 4873.99,5174 U11.1
$1N25550: U13.1 U15.4 | length 197.8
  Bottom Layer w6: U13.1 4063.27,5076.73 U15.4
$1N25556: U15.1 U17.4 | length 1858.3
  Bottom Layer w6: U15.1 4137.46,5054.01 5930.55,5054.01 5933.27,5056.73 U17.4
$1N25562: U17.1 U19.4 | length 246.6
  Bottom Layer w6: U19.4 5991.72,4981.72 U17.1
$1N25568: U19.1 U21.4 | length 355.1
  Bottom Layer w6: U21.4 5571.02,4767.44 5777.43,4767.44 U19.1
$1N25574: U21.1 U23.4 | length 450.5
  Bottom Layer w6: U23.4 5083.46,4770 5434.99,4770 U21.1
$1N26075: U20.1 U22.4 | length 268.6
  Bottom Layer w6: U22.4 4786.19,3587.27 4960.71,3587.27 5003.27,3629.83 U20.1
$1N26088: U10.1 U12.4 | length 677.8
  Bottom Layer w6: U10.1 4898.28,3868.27 U12.4
$1N26091: U12.1 U14.4 | length 640.4
  Bottom Layer w6: U12.1 5151.72,3901.72 U14.4
$1N26094: U8.1 U10.4 | length 654.8
  Bottom Layer w6: U8.1 4556,4450.55 4556,4336 U10.4
$1N26097: U14.1 U16.4 | length 433.6
  Bottom Layer w6: U14.1 5574.57,4288.88 5574.57,4260.69 5571.73,4257.85 U16.4
$1N26100: U16.1 U18.4 | length 340.4
  Bottom Layer w6: U18.4 5538.27,3828.27 U16.1
$1N26103: U18.1 U20.4 | length 298.3
  Bottom Layer w6: U20.4 5159.46,3554 5263.99,3554 U18.1
$1N26106: U5.1 U8.4 | length 348.8
  Bottom Layer w6: U8.4 4304.46,4769 4508.99,4769 U5.1
$1N26109: U5.4 U23.1 | length 465.5
  Bottom Layer w6: U5.4 4643.46,4770 5009.99,4770 U23.1
$1N26112: U22.1 U24.4 | length 395.1
  Bottom Layer w6: U24.4 4468.27,3798.6 4698.59,3568.28 U22.1
$1N29399: C12.2 CARD1.C3 D7.1 R11.2 | length 450.6
  Top Layer w6: R11.2 3825.34,4277.9 3809.73,4262.29 ; CARD1.C3 3825.4,4197.16 C12.2 3809.73,4262.29 ; D7.1 3921.33,4247.4 3906.44,4262.29 3809.73,4262.29
$1N32608: C14.2 CARD1.C7 D7.3 R17.2 | length 464.1
  Top Layer w6: CARD1.C7 3875.4,4145.87 ; C14.2 3858.3,4210.86 3858.3,4162.97 3875.4,4145.87 ; R17.2 4030.34,4205.43 4015.1,4190.19 4005.35,4190.19 D7.3 3987.76,4170.44 3948.98,4170.44 3924.4,4145.87 3875.4,4145.87
$1N32620: C11.2 CARD1.C2 D7.4 R10.2 | length 580.9
  Top Layer w6: CARD1.C2 3925.4,4115.4 3962.79,4152.79 4015.1,4152.79 4034.91,4172.6 D7.4@4072.49,4172.6 ; D7.4 D7.4@4072.49,4172.6 ; R10.2@4235.34,4330 4235.34,4287.9 C11.2 4142.56,4280 4060,4280 4049.63,4269.63 4049.63,4195.45 D7.4@4072.49,4172.6
$1N42623: D6.1 R16.1 SW2.2 | length 275.6
  Top Layer w6: SW2.2 3750.04,4579.49 R16.1 3750.34,4494.34 D6.1
$1N42777: D5.1 R15.1 SW1.2 | length 275.6
  Top Layer w6: SW1.2 3750.04,4675.51 R15.1 3750.34,4760.66 D5.1
ADC0: C5.2 R4.2 R5.2 U3.9 | length 411.8
  Top Layer w6: R5.2 R4.2 4532.9,4530.34 C5.2 4542.56,4532.44 4641.61,4433.39 U3.9
BOOT: BOOT.1 U3.82 | length 1530.1
  Top Layer w6: U3.82 v1(5176.56,4401.89) ; v1(6390,4920) 6436.89,4920 BOOT.1
  Bottom Layer w6: v1(5176.56,4401.89) 5223.98,4401.89 5237.09,4415 5915.31,4415 6390,4889.69 v1(6390,4920)
DBG_RX: U3.38 UART0_RX.1 | length 1424.3
  Top Layer w6: U3.38 5101.61,4823.08 5129.69,4795 v1(5145,4795) ; v1(6390,4800) 6390.57,4800.57 UART0_RX.1
  Inner2 w6: v1(5145,4795) 5186.49,4753.51 6343.51,4753.51 v1(6390,4800)
DBG_TX: U3.39 UART0_TX.1 | length 1459.8
  Top Layer w6: U3.39 5058.31,4811.69 5075,4795 v1(5100,4795) ; v1(6390,4741.51) UART0_TX.1
  Inner2 w6: v1(5100,4795) 5153.49,4741.51 v1(6390,4741.51)
GND: C4.1 C5.1 C9.1 C10.1 C11.1 C12.1 C14.1 C15.2 C16.1 C17.1 C18.1 C19.1 C20.1 C21.1 C22.1 C23.1 CARD1.8 CARD1.9 CARD1.10 CARD1.11 CARD1.C5 D1.1 D3.1 D4.1 D5.2 D6.2 D7.2 D8.1 GND.1 P1.1 Q1.2 Q2.2 R2.1 R3.1 R5.1 R6.2 R19.1 R23.2 R27.2 RF1.2 RF1.3 RF1.4 RF2.2 RF2.3 RF2.4 SW1.1 SW2.1 U1.3 U3.1 U3.10 U3.27 U3.34 U3.36 U3.37 U3.40 U3.41 U3.45 U3.46 U3.47 U3.48 U3.70 U3.71 U3.72 U3.73 U3.88 U3.89 U3.90 U3.91 U3.92 U3.93 U3.94 U3.95 U4.3 U5.3 U7.3 U8.3 U9.3 U10.3 U11.3 U12.3 U13.3 U14.3 U15.3 U16.3 U17.3 U18.3 U19.3 U20.3 U21.3 U22.3 U23.3 U24.3 USB1.1 USB1.12 USB1.13 USB1.14 | length 14644.7
  Top Layer w6: SW1.1 v1(3650.21,4964.49) ; 3739.65,4039.17 3739.65,4137.09 C12.1 ; C14.1 3927.02,4182.44 v1@3929.79,4185.21 ; v1(3934.06,4225) 3949.06,4210 D7.2 ; v1(4025,4862.44) 4025,4907.44 C21.1 ; CARD1.C5 4075.4,4065.4 ; RF1.3 4155,5428.07 RF1.4 4213.07,5370.98 RF1.2 ; v1(4140,4182.44) C11.1 ; C20.1 4270,5021.27 4296.7,5047.97 4296.7,5086.91 4270,5113.61 C19.1 v1(4270,5197.4) ; CARD1.10 CARD1.11 CARD1.8 3777.99,4057.51 4067.51,4057.51 4075.4,4065.4 ; C9.1 C10.1 ; v1(4315,4039.17) CARD1.9 4100.83,4039.17 4075.4,4064.6 4075.4,4065.4 ; v1(4645,4390.08) U3.10 ; U3.1 4764.84,4779.84 v1(4780,4795) ; v1(4777.72,4567.24) U3.48 ; v1(4777.72,4614.49) U3.47 ; v1(4777.72,4661.73) U3.46 ; v1(4777.72,4708.98) U3.45 ; U3.95 4800,4179.02 v1(4800,4245) ; C18.1 C17.1 C16.1 5083.68,5095.33 v1(5126.54,5095.33) D8.1 ; v1(4884.02,4716.57) 4884.02,4690.35 U3.73 ; U3.72 v1(4920.51,4790.99) ; v1(4933.23,4520) U3.90 ; U3.71 v1(4967.76,4790.99) ; U3.41 4971.69,4899.96 v1(4991.73,4920) ; v1(4979.57,4407.79) U3.91 ; U3.89 v1(4979.57,4637.21) ; v1(5015,4716.08) U3.70 ; U3.40 5015,4900 v1(5035,4920) ; v1(5049.67,4407.03) 5049.67,4448.37 U3.92 ; U3.93 5064.01,4533.58 v1(5098.71,4533.58) ; U3.94 v1(5050.43,4637.21) ; v1(5095.98,4684.87) 5140.5,4684.87 U3.88 ; U3.37 5144.92,4824.77 5174.69,4795 v1(5186.21,4795) ; U3.36 5188.23,4816.77 5210,4795 v1(5220,4795) ; U3.27 5373.39,4433.39 5395,4455 v1(5395,4475) ; U3.34 5373.46,4736.54 v1(5395,4715) ; v1(5640,5075) C23.1 ; v1(5645,4345.76) 5634.24,4345.76 5630,4350 5630,4381.28 R23.2 5590.27,4350 5505,4350 5494.01,4339.01 5494.01,4285.06 5499.27,4279.8 5591.32,4279.8 R27.2 5629.66,4245.34 v1(5660,4215) ; RF2.3 5745,5418.07 RF2.4 5803.07,5360.98 RF2.2 5865,5298.07 v1(5865,5210) C22.1 ; Q2.2 5803.03,4231.11 5746.18,4287.96 5746.18,4336.25 5751.44,4341.52 5779.83,4341.52 5803.03,4364.72 Q1.2 ; C15.2 5899.37,3868.88 P1.1 ; D4.1 6140.26,3688.22 6125.53,3673.49 6125.53,3620.56 R2.1 ; D3.1 v1(6170,3819.62) ; R3.1 6157.04,3885.22 v1(6199.46,3885.22) USB1.12 6273.01,3907.86 USB1.14@6294.66,3929.51 ; D1.1 6377.33,4226.4 U1.3 6424.87,4226.4 6448.56,4202.71 6492.29,4202.71 6498.74,4196.26 ; USB1.1 6190.19,3633.25 R2.1 ; GND.1 v1(6438.21,4503.5) v1(6438.21,4402.09) v1(6438.21,4353.26) 6438.21,4314.35 C4.1 6498.74,4253.82 6498.74,4196.26 ; USB1.13@6460.02,3588.96 6294.66,3588.96 6289.05,3594.57 R2.1 ; USB1.14@6460.02,3929.51 6460.02,4080.36 R6.2 6510,4130.34 6510,4185 6498.74,4196.26
  Bottom Layer w6: U13.3 4193.27,5416.73 U9.3 ; U15.3 4203.27,4903.27 U8.3 ; U10.3 4478.27,4306.73 4185.43,4599.57 4185.43,4815.86 4203.27,4833.7 U8.3 ; U24.3 4511.73,3828.27 4664.15,3675.85 ; U5.3 4584.81,4878.27 ; U22.3 4664.15,3675.85 ; U11.3 4893.27,5291.73 U9.3 ; v1(4920.51,4790.99) v1(4967.76,4790.99) 4997.53,4790.99 U23.3 5013.27,4848.81 5042.73,4878.27 ; U12.3 5036.73,3789.66 ; U7.3 5123.27,5311.73 ; U21.3 5509.81,4878.27 ; U14.3 5556.73,3900.19 U16.3 5278.27,3621.73 U18.3 5090.34,3789.66 5036.73,3789.66 ; U19.3 5813.27,4878.27 ; U17.3 5813.27,4878.27 ; U4.3 5938.27,5311.73 5123.27,5311.73 ; U8.3 4244.81,4878.27 4584.81,4878.27 ; 4584.81,4878.27 5042.73,4878.27 ; 4664.15,3675.85 4665.03,3676.73 U20.3 5036.73,3710.19 5036.73,3789.66 ; U9.3 5021.31,5416.73 5039.15,5434.57 5064.31,5434.57 5085,5413.88 5085,5350 5123.27,5311.73 ; 5042.73,4878.27 5509.81,4878.27 ; 5509.81,4878.27 5813.27,4878.27
  other v1: 6220,3568.76 6043.76,3588.58 6090,3590 6220,3615 6043.76,3640.44 6090,3640.82 6043.76,3690.61 6090,3690.8 6044.53,3734.63 6090,3734.63 4315,3833.01 5821.46,3865.29 5936.08,3865.29 5990,3865 4315,3905 5821.46,3909.61 5936.08,3909.61 6200.62,3929.51 4665,3944.8 3650,3946.91 5821.46,3953.93 5860,3955 5900,3955 4315,3975 3650,3990 5821.46,3998.24 5860,4000 6412.05,4025 6470,4025 3650,4028.65 3650,4075 6412.05,4075.72 3650,4120.77 4240,4125 4185,4126.03 3650,4170 3700,4170 3934.06,4185.21 4430,4209.01 3580,4231.45 4430,4255 4326.36,4261.15 4615,4265 4454.16,4277.47 3640,4290 4340.65,4325.59 4405.33,4325.59 4455,4325.78 4614.35,4325.78 6478.17,4353.26 4030,4390 4144.35,4392.17 4239.02,4392.17 4338.7,4392.17 4422.01,4395.99 4503.05,4395.99 6478.17,4402.09 3840,4450 5623.28,4495 3840,4515 4285,4590 4605,4590 4340,4631.39 4535.16,4635.16 3868.27,4775 3835,4815 3977.14,4861.21 4069.99,4861.21 4109.77,4861.21 3695,4965 4325,4990 3695,5000 3650,5001.88 4774.55,5012.47 5243.79,5095.33 5327.17,5095.33 4773.05,5097.52 4909.72,5097.52 5016.11,5097.52 5565,5115 4330,5120 4326.88,5197.4
GNSS_ANT: C20.2 R22.1 U3.2 | length 788.9
  Top Layer w6: R22.1 4269.91,4932.53 C20.2
  Top Layer w23: R22.1 4160,4895 ccw(c4320.26,4895) 4315.13,4734.82 ccw(c4320.26,4895) 4324.96,4734.81 ; 4324.99,4734.81 ccw(c4366.19,38318.96) U3.2
GNSS_VCC: C19.2 L1.1 U3.8 | length 1040.1
  Top Layer w6: L1.1@4216.52,5204.46 4220,5200.98 v1(4220,5025) 4262.44,5067.44 C19.2 ; v1(4645,4475) 4708.19,4475 U3.8
  Inner2 w6: v1(4220,5025) 4220,4900 v1(4645,4475)
LTE_ANT: C22.2 R29.1 U3.35 | length 805.4
  Top Layer w6: R29.1 5752.59,5117.44 C22.2
  Top Layer w23: U3.35 5572.5,4779.84 ccw(c5572.5,4959.84) 5752.5,4959.84 R29.1
NET_STATUS: R26.1 U3.16 | length 718.2
  Top Layer w6: U3.16 4928.39,4126.61 4945,4110 v1(5228.05,4110) ; v1(5505,4205) 5520,4220 R26.1
  Inner2 w6: v1(5228.05,4110) v1@5410,4110
  Bottom Layer w6: v1(5415,4110) 5505,4200 v1(5505,4205)
POWER_OFF: OFF.1 U3.15 | length 1892.8
  Top Layer w6: v1(4875,4242.95) 4882.13,4242.95 4885.08,4240 U3.15 ; v1(6390,4860) 6437.83,4860 OFF.1
  Bottom Layer w6: v1(4875,4242.95) 5006.05,4374 5213.06,4374 5242.06,4403 5933,4403 v1(6390,4860)
PWM0: R34.2 U3.26 | length 234.3
  Top Layer w6: U3.26 5370.08,4390.08 v1(5450,4470)
  Bottom Layer w6: v1(5450,4470) 5479.51,4499.51 5501.31,4499.51 5506.07,4504.27 R34.2
PWR_KEY: R15.2 U3.7 | length 1002.1
  Top Layer w6: R15.2 3824.47,4660.99 4583.7,4660.99 4655,4589.69 4655,4526 4661,4520 U3.7
RX: RX.1 U3.17 | length 1730.1
  Top Layer w6: U3.17 v1(4971.69,4240) ; v1(6390,4680) 6435.75,4680 RX.1
  Bottom Layer w6: v1(4971.69,4240) 5093.69,4362 5218.03,4362 5247.03,4391 6131.31,4391 6390,4649.69 v1(6390,4680)
SIM_CLK: R11.1 U3.13 | length 885.3
  Top Layer w6: R11.1 3925,4325 v1(3940,4310) ; v1(4640,4230.98) 4640,4245 4655,4260 4709.72,4260 U3.13
  Inner2 w6: v1(3940,4310) 4020,4230 4639.02,4230 v1(4640,4230.98)
SIM_DATA: R17.1 U3.11 | length 632.7
  Top Layer w6: R17.1 4109.65,4344.99 4209.74,4344.99 4215.74,4350.99 4314.26,4350.99 4318.48,4346.77 U3.11
SIM_DET: CARD1.CD R18.1 U3.79 | length 1139.9
  Top Layer w6: CARD1.CD 4392.57,4092.09 R18.1 4609.41,4084.66 4644.27,4049.8 4714.8,4049.8 4715,4050 4820.47,4050 4907.59,4137.12 4907.59,4219.56 4897.75,4229.41 4897.75,4317.21 4917.69,4337.15 4917.69,4377.31 4893.11,4401.89 U3.79
SIM_RST: R10.1 U3.12 | length 426.2
  Top Layer w6: R10.1@4294.66,4330 4321.2,4303.46 U3.12
SIM_VCC: C9.2 C10.2 CARD1.C1 D7.5 U3.14 | length 1121.2
  Top Layer w6: D7.5 4206.44,4210 4234,4182.44
  Top Layer w10: CARD1.C1 4025.4,4120.4 4055.79,4150.79 4202.35,4150.79 4234,4182.44 C9.2 C10.2 4642.56,4182.44 4715,4110 4825,4110 4841.77,4126.77 U3.14
SPI0_MOSI: R33.2 U3.50 | length 811.4
  Top Layer w6: v1(4781.34,4473.23) 4817.68,4473.23 U3.50
  Bottom Layer w6: v1(4781.34,4473.23) 5363.54,4473.23 5485.31,4595 R33.2
STATUS: R20.1 U3.25 | length 215.9
  Top Layer w6: U3.25 5481.27,4346.77 R20.1
TX: TX.1 U3.18 | length 1644.5
  Top Layer w6: U3.18 v1(5015,4240) ; v1(6390,4620) 6393.4,4623.4 TX.1
  Bottom Layer w6: v1(5015,4240) 5125,4350 5223,4350 5252,4379 6149,4379 v1(6390,4620)
USB_N: D4.2 U3.60 USB1.5 USB1.7 | length 1510
  Top Layer w6: U3.60 5211.85,4377.19 5183.18,4348.52 5183.18,4313.52 5190.16,4306.54 5235.26,4306.54 5240.52,4301.28 5240.52,4300.91 5250,4291.43 5250,4250.44 5337.44,4163 5730.03,4163 6140.26,3752.77 D4.2 ; 6249.6,3729.71 6240.38,3738.93 6240.38,3759.84 6249.77,3769.23 6272.86,3769.23 USB1.7
  Top Layer w10: D4.2 6153.88,3728.69 6272,3728.69 USB1.5
USB_P: D3.2 U3.59 USB1.6 USB1.8 | length 1509.4
  Top Layer w6: U3.59 5227.75,4331.02 5262,4296.77 5262,4255.41 5342.41,4175 5735,4175 5931.57,3978.43 ccw(c5947.48,3994.34) 5963.39,3978.43 5964.07,3979.11 cw(c5979.98,3963.2) 5995.89,3947.29 5995.21,3946.61 ccw(c6011.12,3930.7) 6027.03,3914.79 6027.71,3915.47 cw(c6043.62,3899.56) 6059.53,3883.65 6058.85,3882.97 ccw(c6074.76,3867.06) 6058.85,3851.15 6123.84,3786.16 D3.2 ; USB1.6 6297.65,3749.39 6303.65,3755.39 6303.65,3783.23 6297.65,3789.23 6273.49,3789.23 USB1.8
  Top Layer w10: D3.2@6142.86,3788.76 USB1.8
VBAT: C15.1 C16.2 C17.2 C18.2 D8.2 LED9.2 LED16.2 P1.2 R4.1 U1.5 U3.42 U3.43 U4.2 U5.2 U7.2 U8.2 U9.2 U10.2 U11.2 U12.2 U13.2 U14.2 U15.2 U16.2 U17.2 U18.2 U19.2 U20.2 U21.2 U22.2 U23.2 U24.2 | length 14130.8
  Top Layer w20: R4.1@4430,4589.66 4435,4594.66 v1(4435,4630) ; 4884.18,5027.44 4885.08,5026.54 U3.43 ; U3.42 4928.39,4995.38 C17.2 ; C16.2 5159.89,5027.44 D8.2 ; v1(5540,4660) 5946.47,4660 6014.99,4591.48 6014.99,4582.64 6046.74,4550.89 6046.74,4448.38 ; LED9.2 6044.83,4446.48 6046.74,4448.38 ; U1.5 6129.87,4306.31 LED16.2 6014.99,4329.41 6046.74,4361.16 6046.74,4448.38
  Top Layer w40: C18.2 4884.18,5027.44 C17.2 C16.2 ; C15.1 5731.75,3858.88 P1.2
  Inner2 w20: v1(4435,4630) 4450.41,4630 4706.52,4373.9 5258.28,4373.9 ; 5280.91,4351.27 5295,4351.27
  Inner2 w40: v1(4964.94,3960) v1(5028.95,3960) v1(5084.3,3960) v1(5145,3960) 5603.79,3960 v1(5615,3948.79) ; v1(5125,5025) v1(5125,4988.41) v1(5125,4957.02) 5125,4873.73 5062.01,4810.74 5062.01,4779.26 5160,4681.27 5160,4617.16 ; v1(5540,4660) 5202.84,4660 5160,4617.16 ; v1(5657.25,3993.1) 5639.08,3993.1 5280.91,4351.27 5258.28,4373.9 5160,4472.18 5160,4617.16
  Bottom Layer w20: U13.2 4095,5251.54 4095,5210 4150,5155 ; U15.2 4111.73,5116.73 4150,5155 ; U8.2 4290,4750 4555,4750 ; U24.2@4460,3860 4453.11,3853.11 4452.79,3853.11 4435,3835.32 4435,3805 4696.56,3543.44 4753.75,3543.44 4771.73,3561.42 U22.2 5033.85,3568.27 ; U10.2 4548.27,4273.27 4575,4300 ; U5.2 4576.73,4771.73 4555,4750 ; U12.2 4891.91,3901.73 4833.64,3960 ; U20.2 5036.73,3571.15 5033.85,3568.27 ; U23.2 5046.73,4766.42 5035.31,4755 ; U9.2 5051.73,5266.73 4975,5190 4930,5190 U11.2 4925.86,5192.4 4925.86,5169.14 4940,5155 ; v1(5084.3,3960) v1(5028.95,3960) v1(4964.94,3960) 4833.64,3960 ; U7.2 5156.73,5175 5136.73,5155 ; U21.2 5501.73,4771.73 5480,4750 5040.31,4750 5035.31,4755 ; U14.2 5523.27,4328.27 5545,4350 5595,4350 5615,4330 v1(5615,3993.1) v1(5615,3948.79) v1(5615,3904.47) 5615,3883.43 5579.84,3848.27 U16.2 5571.73,3815.85 5322.77,3566.89 ; U4.2 5991.73,5159.37 ; 4150,5155 4940,5155 ; 4555,4750 4556.56,4748.44 ; 4556.56,4748.44 5028.75,4748.44 ; 4556.56,4748.44 4575,4730 4575,4300 ; 4575,4300 4575,4218.64 4833.64,3960 ; 4940,5155 5136.73,5155 ; 5028.75,4748.44 5035.31,4755 ; 5028.75,4748.44 5818.44,4748.44 5846.73,4776.73 U19.2 5875.01,4803.27 6030,4958.26 6030,5036.73 6010,5056.73 U17.2 5991.73,5159.37 ; 5033.85,3568.27 5116.73,3568.27 5150,3535 5310.31,3535 5322.77,3547.46 5322.77,3566.89 ; 5136.73,5155 5987.36,5155 5991.73,5159.37 ; 5322.77,3566.89 5313.11,3566.89 U18.2 5321.73,3568.27 5322.77,3567.23 5322.77,3566.89
  other v1: 5615,3860.15 5657.25,3860.15 5657.25,3904.47 5657.25,3948.79 5699.5,3993.1 5741.75,3993.1 5072.97,4957.02 5174.83,4957.02 5072.2,4988.41 5210,5000
VBUS: C4.2 D1.2 R13.2 U1.4 U1.8 U3.61 USB1.2 USB1.11 | length 3006.5
  Top Layer w20: U3.61 5222.33,4435.99 v1(5251.85,4435.99) ; R13.2 5897.99,4077.01 5926.34,4048.66 6082.05,4048.66 6096.69,4063.31 ; 6105,4055 6096.69,4063.31 ; U1.8 6136.65,4126.4 6096.69,4086.44 6096.69,4063.31 ; v1(6220,3664.75) USB1.2 ; USB1.11 v1(6220.51,3853.73) 6133.05,3853.73 6102.95,3883.82 6105,3885.88 6105,4015.03 6105.59,4015.62 6105.59,4055 v1(6295,4055) ; D1.2 6321.44,4343.74 6344.7,4320.48 ; v1(6344.7,4375) 6344.7,4320.48 ; C4.2 6446.61,4250.83 6445.66,4250.83 6436.3,4260.19 6436.3,4261.14 6421.04,4276.4 U1.4 6344.7,4320.48
  Inner2 w20: v1(5251.85,4435.99) 5914.01,4435.99 v1(6295,4055) 6344.7,4104.7 v1(6344.7,4375)
  Bottom Layer w20: v1(6220,3664.75) 6220,3853.21 v1(6220.51,3853.73)
VDD_EXT: R18.2 U3.24 VDD_EXT.1 | length 3322
  Top Layer w6: R18.2 4410.34,4015 v1(4455,4015) ; U3.24 v1(5385,4303.46) ; v1(6390,4977.73) VDD_EXT.1
  Inner2 w6: v1(4455,4015) v1(4845,4015)
  Bottom Layer w6: v1(5385,4303.46) 5096.54,4015 v1(4845,4015) 4845,4242.64 5059.34,4456.98 5260.55,4456.98 5268.52,4449.01 5889.32,4449.01 6390,4949.69 v1(6390,4977.73)
WAKEUP_KEY: R16.2 U3.101 | length 1213.8
  Top Layer w6: R16.2 3883.37,4505.48 4552.55,4505.48 4645.43,4412.59 4750.24,4412.59 4772.41,4390.43 4772.41,4377.84 4796.47,4353.78 4841.56,4353.78 4873.27,4322.07 U3.101
WS2812_DIN: R33.1 R34.1 U4.4 | length 1368.3
  Bottom Layer w6: R33.1 R34.1 5603.83,4465.83 5889.17,4465.83 6060,4636.66 6060,5245 6013.27,5291.73 U4.4
pads on no net: CARD1.C6 D7.6 SCREW1.1 SCREW2.1 SCREW3.1 SCREW4.1 U1.1 U1.6 U1.9 U3.3 U3.4 U3.5 U3.6 U3.19 U3.20 U3.21 U3.22 U3.23 U3.28 U3.29 U3.30 U3.31 U3.32 U3.33 U3.44 U3.49 U3.51 U3.52 U3.53 U3.54 U3.55 U3.56 U3.57 U3.58 U3.62 U3.63 U3.64 U3.65 U3.66 U3.67 U3.68 U3.69 U3.74 U3.75 U3.76 U3.77 U3.78 U3.80 U3.81 U3.83 U3.84 U3.85 U3.86 U3.87 U3.96 U3.97 U3.98 U3.99 U3.102 U3.103 U3.104 U3.105 U3.106 U3.107 U3.108 U3.109 U6.2 U24.1 USB1.3 USB1.9

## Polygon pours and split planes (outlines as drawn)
GND on Bottom Layer (solid, remove dead copper, pour order 2): 3340,5675 6725,5675 6725,3340 3340,3340
GND on Top Layer (solid, remove dead copper, pour order 0): 3375,5620 6700,5620 6700,3395 3375,3395
GND on Inner1 (solid, remove dead copper): 3000,6030 7065,6030 7065,3000 3000,3000
VBAT on Inner2 (solid, remove dead copper): 5595,4010 5760.91,4010 5760.91,3841.13 5595,3841.13
GND on Inner2 (solid, remove dead copper): 3175,5840 6915,5840 6915,3165 3175,3165
VBAT on Inner2 (solid, remove dead copper): 5224.1,4944.34 5224.1,5045 5219.1,5050 5056.45,5050 5052.45,5045.32 5052.45,4943.6 5223.36,4943.6

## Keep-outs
Top Layer:
  region: 3845,5010 3845,5515 4030,5515 4030,5010
  region: 4703.53,4878.27 5326.02,4878.27 5326.02,4169.61 4703.53,4169.61
  region: 4955,4935 5235,4935 5235,4910 4955,4910
  region: 5370,4490 5412.65,4490 5412.65,4435.99 5370,4435.99
  region: 5689.88,5417.09 5802.1,5417.09 5802.1,5308.8 5689.88,5308.8
  region: 4099.88,5427.09 4212.1,5427.09 4212.1,5312.9 4099.88,5312.9
  region: 3505.1,4941.11 3648.9,4941.11 3648.9,4698.89 3505.1,4698.89
  region: 6193.57,4301.79 6354.99,4301.79 6354.99,4101.01 6193.57,4101.01
  region: 3912.95,4236.78 3957.02,4236.78 3957.02,4170.44 3912.95,4170.44
  region: 6128.45,3694.08 6160.31,3694.08 6160.31,3678.76 6128.45,3678.76
  region: 6421.04,4238.61 6500,4238.61 6500,4100 6421.04,4100
  region: 6158.34,4101.01 6327.6,4101.01 6327.6,4075.41 6158.34,4075.41
  region: 6156.01,3836.75 6240,3836.75 6240,3800 6156.01,3800
  region: 6125,4040 6176.24,4040 6176.24,3957.34 6125,3957.34
  region: 4650,4215 4777.55,4215 4777.55,4121.24 4650,4121.24
  region: 4110,4200 4160.62,4200 4160.62,4158.85 4110,4158.85
  region: 3508.1,4556.11 3651.9,4556.11 3651.9,4313.89 3508.1,4313.89
  region: 4319.53,4338 4662.52,4338 4662.52,4311.73 4319.53,4311.73
  region: 4184.03,5170.23 4242.05,5170.23 4242.05,4948.97 4184.03,4948.97
  region: 6112.45,3812.5 6119.95,3819.86 6119.95,3866.83 6105.59,3881.18 6105.59,4069.95 6035.54,4140 5791.02,4140
Bottom Layer:
  region: 5043.74,4441.38 5229.49,4441.38 5229.49,4378.27 5043.74,4378.27
  region: 5027.03,4449.13 5229.49,4449.13 5229.49,4378.27 5027.03,4378.27
Board Outline Layer:
  lines w10: 3490,3628.11 ccw(c3608.11,3628.11) 3608.11,3510 6442.76,3510 ccw(c6442.76,3628.11) 6560.87,3628.11 6560.87,5399.76 ccw(c6442.76,5399.76) 6442.76,5517.87 3608.11,5517.87 ccw(c3608.11,5399.76) 3490,5399.76 3490,3628.11

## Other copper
Top Layer:
  region net VBAT: 5595,4010 5760.91,4010 5760.91,3841.13 5595,3841.13
  region net GND: 5800,3843.84 5800,4019.7 5860.3,4019.7 6015,3865 6015,3843.84
  region net VBAT: 4830,5045 4830,5003.85 4833.57,5000.27 4865.74,5000.27 4865.74,4919.73 4949.73,4919.73 4950,4920 4950,4944.34 5224.1,4944.34 5224.1,5042.48 5215.05,5050 4835,5050

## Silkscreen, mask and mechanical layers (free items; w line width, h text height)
Bottom Solder Mask Layer:
  region: 6193.57,4301.79 6354.99,4301.79 6354.99,4101.01 6193.57,4101.01
Mechanical Layer:
  drawing of 1984 lines, arcs and shapes, not listed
